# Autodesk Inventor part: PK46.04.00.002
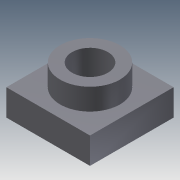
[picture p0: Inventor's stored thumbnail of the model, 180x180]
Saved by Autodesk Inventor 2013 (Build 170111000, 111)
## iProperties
Shininess: 64.0
Length Units: 11269
Angle Units: 11279
Time Units: 11290
Mass Units: 11283
Length Display Precision: 3
Angle Display Precision: 2
Compacted: True
Part Number: PK46.04.00.002
Document SubType Name: Modeling
Created: 2004-12
Material: Steel, Mild
Designer: Salex
Manufacturer: Standard
Standards Organization: Custom
Density: 7.86 g/cm^3
Density: 0.0
Volumn: 0.0
Area: 0.0
PropertySet Name: Model Information
Control State: 0
Master: False
Checked Out: False
Checked Out Date: 2008-10-15
Last Check In Date: 2008-10-15
Author: Salex
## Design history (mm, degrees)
sketch "Sketch1"
  geometry: L1 (0, 0)-(70, 0); L2 (70, 0)-(70, 70); L3 (70, 70)-(0, 70); L4 (0, 70)-(0, 0); C1 r 15 at (35, 35)
  constraints: 8 end point, 2 parallel, 1 centre point, 1 horizontal, 1 perpendicular, 1 other
  dimensions: "d0" = 70 distance of L1.start L1.end; "d1" = 70 distance of L3.end L1.start (= d0); "d2" = 30 diameter of C1; "d3" = 35 distance from line of C1.centre L3 (= 0.5 x d0); "d4" = 35 distance from line of L4 C1.centre (= d3)
extrude "Extrusion1" new body sketch "Sketch1" distance "d5" = 22; taper "d6" = 0 deg
sketch "Sketch2"
  geometry: C1 r 15 at (35, 35) reference; C2 r 25 at (35, 35)
  constraints: 1 centre point, 1 coincident
  dimensions: "d7" = 50 diameter of C2
extrude "Extrusion2" join sketch "Sketch2" distance "d8" = 18; taper "d9" = 0 deg
body "Solid1"
